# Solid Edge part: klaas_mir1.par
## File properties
Last saved by: Cymax
Revision: 52
Accuracy: 0,990
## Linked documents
klaas.par
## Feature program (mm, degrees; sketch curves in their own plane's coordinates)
part copy "CopiedPart_1"
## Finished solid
Body 1: solid body, 39 faces, 96 edges, 64 vertices.
  Faces by surface: plane 23, cylinder 8, torus 8
  Edges by curve: line 56, circle 28, intersection 12
Bounding box of the edges (mm; curved faces can reach further): 1221.056 x 180.674 x 352.473, from (235.5991, 526.7275, -344.4289) to (1456.6554, 707.4018, 8.0446).
Cylindrical faces by radius (mm): R430.6294 x1, R437.3201 x1, R450.6294 x1, R457.3201 x1, R658.028 x2, R678.028 x2
Toroidal faces (ring radius, tube radius in mm): R478.028 r180 x4, R478.028 r200 x4
Planar faces by outward normal: +x 6, -x 6, oblique 11
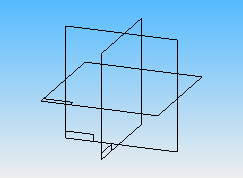
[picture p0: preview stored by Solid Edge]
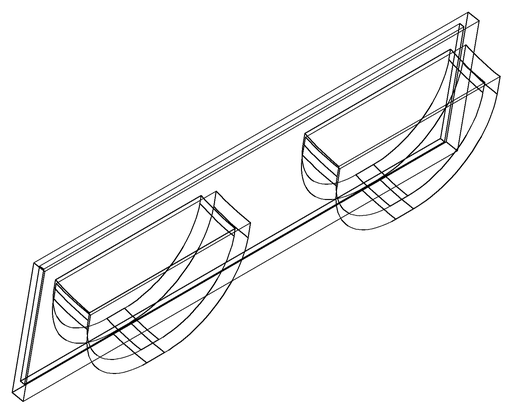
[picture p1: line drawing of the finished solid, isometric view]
